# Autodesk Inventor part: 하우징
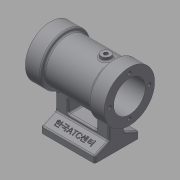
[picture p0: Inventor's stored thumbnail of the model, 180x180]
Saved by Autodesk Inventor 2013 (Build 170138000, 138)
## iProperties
Created: 2018-01
Part Number: 하우징
Material: 알루미늄 6061
Document SubType Name: Modeling
Designer: mduedu
Density: 1 g/cm^3
Author: mduedu
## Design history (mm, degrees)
sketch "스케치1"
  geometry: L1 (-25, 0)-(25, 0); L2 (-25, 0)-(-25, 16); L3 (-25, 16)-(-15, 16); L4 (-15, 16)-(-15, 14); L5 (-15, 14)-(15, 14); L6 (15, 14)-(15, 16); L7 (15, 16)-(25, 16); L8 (25, 16)-(25, 0); 2 further points
  constraints: 16 end point, 3 parallel, 2 collinear, 2 perpendicular, 1 coincident, 1 horizontal, 1 midpoint, 1 vertical
  dimensions: "d0" = 50 distance of L1.start L1.end; "d2" = 10 distance of L2.end L3.end; "d3" = 10 distance of L6.end L7.end (= d2); "d4" = 32 diameter of L3 L1; "d5" = 28 diameter of L5 L1
revolve "회전1" sketch "스케치1" stored, may be unused: angle "d6" = 90 deg
hole "구멍1" diameter "d9" = 20; stored, may be unused: countersink angle "d13" = 90 deg, drill point angle "d15" = 118 deg; dims "d7" = 10, "d8" = 10, "d10" = 6, "d11" = 4, "d12" = 2, "d14" = 8
fillet "모깎기1" dims "d16" = 1
sketch "스케치2"
  geometry: L1 (0, 0)-(-34, 0); L2 (-34, 14)-(-34, -14); L3 (-34, 14)-(-30, 14); L4 (-30, 14)-(-26, 5); L5 (-26, 5)-(-13.077, 5); L6 (-26, -5)-(-13.077, -5); L7 (-30, -14)-(-26, -5); L8 (-34, -14)-(-30, -14); C1 r 10 at (0, 0) reference; A1 r 14 centre (0, 0) between (-13.077, 5) and (-13.077, -5); 2 further points
  constraints: 16 end point, 3 symmetric about line, 2 perpendicular, 2 point on circle, 1 centre point, 1 coincident, 1 horizontal, 1 midpoint, 1 parallel, 2 other
  dimensions: "d17" = 34 distance of L1.end L1.start; "d18" = 28 distance between parallel lines of L8 L3; "d19" = 10 distance between parallel lines of L6 L5; "d20" = 4 distance of L2.end L7.start; "d21" = 8 distance from line of L6.start L2
extrude "돌출1" join sketch "스케치2" stored distance "d22" = 34; taper "d23" = 0 deg
sketch "스케치3"
  geometry: L1 (-9, -16)-(9, -16); L2 (9, -16)-(9, -24); L3 (9, -24)-(-9, -24); L4 (-9, -24)-(-9, -16); L5 (-17, -15.199)-(-17, -26) reference; L6 (17, -26)-(17, -15.199) reference; L7 (-17, -34)-(17, -34) reference; 1 further point
  constraints: 8 end point, 2 parallel, 1 horizontal, 1 perpendicular
  dimensions: "d24" = 8 distance between parallel lines of L4 L5; "d25" = 8 distance between parallel lines of L2 L6; "d26" = 10 distance between parallel lines of L3 L7; "d27" = 8 distance of L1.end L2.end
extrude "돌출2" cut sketch "스케치3" stored distance "d28" = 34; taper "d29" = 0 deg
fillet "모깎기2" dims "d30" = 1
fillet "모깎기3" dims "d31" = 1
fillet "모깎기4" dims "d32" = 1
fillet "모깎기5" dims "d33" = 1
fillet "모깎기6" dims "d34" = 1
sketch "스케치4"
  geometry: 4 further points
  constraints: 4 other
hole "구멍2" sketch "스케치4" at (-12.5, 0), (0, -12.5), (12.5, 0), (0, 12.5) diameter "d35" = 2.459; stored, may be unused: countersink angle "d39" = 90 deg, drill point angle "d41" = 120 deg; dims "d36" = 5.5, "d37" = 4, "d38" = 2, "d40" = 7
sketch "스케치5"
  geometry: 4 further points
  constraints: 4 other
hole "구멍4" sketch "스케치5" at (-12.5, 0), (0, -12.5), (12.5, 0), (0, 12.5) diameter "d42" = 2.459; stored, may be unused: countersink angle "d46" = 90 deg, drill point angle "d48" = 120 deg; dims "d43" = 5.5, "d44" = 4, "d45" = 2, "d47" = 7
sketch "스케치6"
  geometry: 2 further points
  constraints: 2 other
hole "구멍5" sketch "스케치6" at (7, 14), (25, 14) diameter "d49" = 2.459; stored, may be unused: countersink angle "d53" = 90 deg, drill point angle "d55" = 120 deg; dims "d50" = 6.9, "d51" = 4, "d52" = 2, "d54" = 8.4
node "작업 평면1"
sketch "스케치7"
  geometry: L1 (-25, 16)-(-25, -16) reference; C1 r 3 at (-10, 0); 1 further point
  constraints: 1 centre point, 1 horizontal alignment
  dimensions: "d57" = 6 diameter of C1; "d60" = 15 distance from line of C1.centre L1
extrude "돌출3" join sketch "스케치7" stored distance "d61" = 10; taper "d62" = 0 deg
fillet "모깎기7" dims "d63" = 1
hole "구멍6" diameter "d66" = 2.459; stored, may be unused: countersink angle "d70" = 90 deg, drill point angle "d72" = 118 deg; dims "d64" = 10, "d65" = 10, "d67" = 6, "d68" = 4, "d69" = 2, "d71" = 8
sketch "스케치8"
  geometry: L1 (-1, 0)-(0, 0) reference; L2 (0, 0)-(0, 8.549) reference; L3 (0, 8.549)-(-1, 8.549) reference; L4 (-1, 8.549)-(-1, 0) reference; L5 (32, 0)-(33, 0) reference; L6 (33, 0)-(33, 8.549) reference; L7 (32, 8.549)-(33, 8.549) reference; L8 (32, 8.549)-(32, 0) reference; 3 further points
  constraints: 1 horizontal alignment, 1 midpoint, 1 vertical alignment, 1 other
feature "엠보싱1" sketch "스케치8" dims "d73" = 0.5, "d74" = 0
node "솔리드1"
node "투영된 루프1"
node "투영된 루프2"
node "절단 모서리 투영1"
other parameters: "d56" = 16
